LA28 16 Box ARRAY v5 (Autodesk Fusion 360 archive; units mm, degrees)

design "LA28 16 Box ARRAY" references "LA28 RF1 Sheet Metal Assembly", "LA28 TOUR BLOCK"
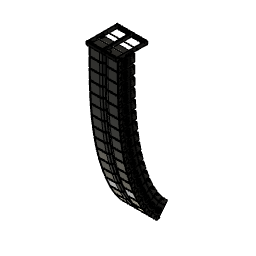
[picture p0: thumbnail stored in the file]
component_insert "Component Insert1"
as_built_joint "As-built1"
component_insert "Component Insert2"
joint "Assemble1" alignAngle 0 alignOffsetX 0 alignOffsetY 0 alignOffsetZ 5.08
component_insert "Component Insert3"
joint "Assemble2" alignAngle -0.5 alignOffsetX 0 alignOffsetY 0 alignOffsetZ 5.08
component_insert "Component Insert4"
component_insert "Component Insert5"
joint "Assemble3" alignAngle -0.5 alignOffsetX 0 alignOffsetY 0 alignOffsetZ 5.08
joint "Assemble4" alignAngle -1 alignOffsetX 0 alignOffsetY 0 alignOffsetZ 5.08
component_insert "Component Insert6"
component_insert "Component Insert7"
component_insert "Component Insert8"
joint "Assemble5" alignAngle -1.5 alignOffsetX 0 alignOffsetY 0 alignOffsetZ 5.08
joint "Assemble6" alignAngle -1.5 alignOffsetX 0 alignOffsetY 0 alignOffsetZ 5.08
joint "Assemble7" alignAngle -2 alignOffsetX 0 alignOffsetY 0 alignOffsetZ 5.08
component_insert "Component Insert9"
joint "Assemble8" alignAngle -2 alignOffsetX 0 alignOffsetY 0 alignOffsetZ 5.08
component_insert "Component Insert10"
joint "Assemble9" alignAngle -2 alignOffsetX 0 alignOffsetY 0 alignOffsetZ 5.08
component_insert "Component Insert11"
component_insert "Component Insert12"
joint "Assemble10" alignAngle -3 alignOffsetX 0 alignOffsetY 0 alignOffsetZ 5.08
joint "Assemble11" alignAngle -3 alignOffsetX 0 alignOffsetY 0 alignOffsetZ 5.08
component_insert "Component Insert13"
joint "Assemble12" alignAngle -3 alignOffsetX 0 alignOffsetY 0 alignOffsetZ 5.08
component_insert "Component Insert14"
component_insert "Component Insert15"
joint "Assemble13" alignAngle -4 alignOffsetX 0 alignOffsetY 0 alignOffsetZ 5.08
joint "Assemble14" alignAngle -5 alignOffsetX 0 alignOffsetY 0 alignOffsetZ 5.08
component_insert "Component Insert16"
component_insert "Component Insert17"
joint "Assemble15" alignAngle -7 alignOffsetX 0 alignOffsetY 0 alignOffsetZ 5.08
joint "Assemble16" alignAngle -9 alignOffsetX 0 alignOffsetY 0 alignOffsetZ 5.08

design "LA28 TOUR BLOCK" references "LA28 TOUR BLOCK.sldprt"
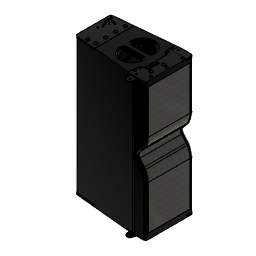
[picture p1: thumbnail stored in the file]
step "WorkingModel"
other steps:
derived_base_feature "Derived Base Feature" bodies "Fillet3"
named bodies: "Fillet3"

design "LA28 RF1 Sheet Metal Assembly" references "la28RF1 SHEET METAL ASSEMBLY.SLDASM"
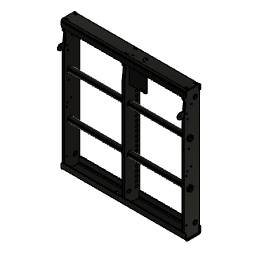
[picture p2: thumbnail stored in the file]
step "WorkingModel"
derived_instance "DerivedInstance1"
derived_instance "DerivedInstance2"
derived_instance "DerivedInstance3"
derived_instance "DerivedInstance4"
derived_instance "DerivedInstance5"
derived_instance "DerivedInstance6"
derived_instance "DerivedInstance7"
as_built_joint "As-built1"
offset_faces "OffsetFaces1" distance 0.7595 (= "0.1644 in - 0.1345 in")
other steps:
derived_base_feature "Derived Base Feature1"
derived_base_feature "Derived Base Feature1" bodies "Cut-Extrude3"
derived_base_feature "Derived Base Feature1" bodies "Cut-Extrude3"
derived_base_feature "Derived Base Feature1" bodies "Boss-Extrude1"
derived_base_feature "Derived Base Feature1" bodies "Cut-Extrude2"
derived_base_feature "Derived Base Feature1" bodies "Boss-Extrude1"
derived_base_feature "Derived Base Feature1" bodies "Cut-Extrude2"
derived_base_feature "Derived Base Feature1" bodies "Mirror2"
create_component "CreateComponent1"
create_component "CreateComponent2"
create_component "CreateComponent3"
create_component "CreateComponent4"
create_component "CreateComponent5"
create_component "CreateComponent6"
create_component "CreateComponent7"
named bodies: "Cut-Extrude3", "Cut-Extrude2", "Mirror2", "Boss-Extrude1"

design "la28RF1 SHEET METAL ASSEMBLY.SLDASM"
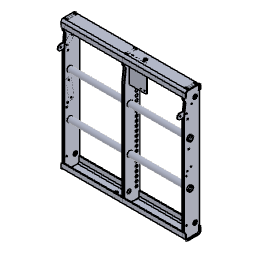
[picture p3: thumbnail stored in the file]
named bodies: "Cut-Extrude3", "Cut-Extrude2", "Mirror2", "Boss-Extrude1"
